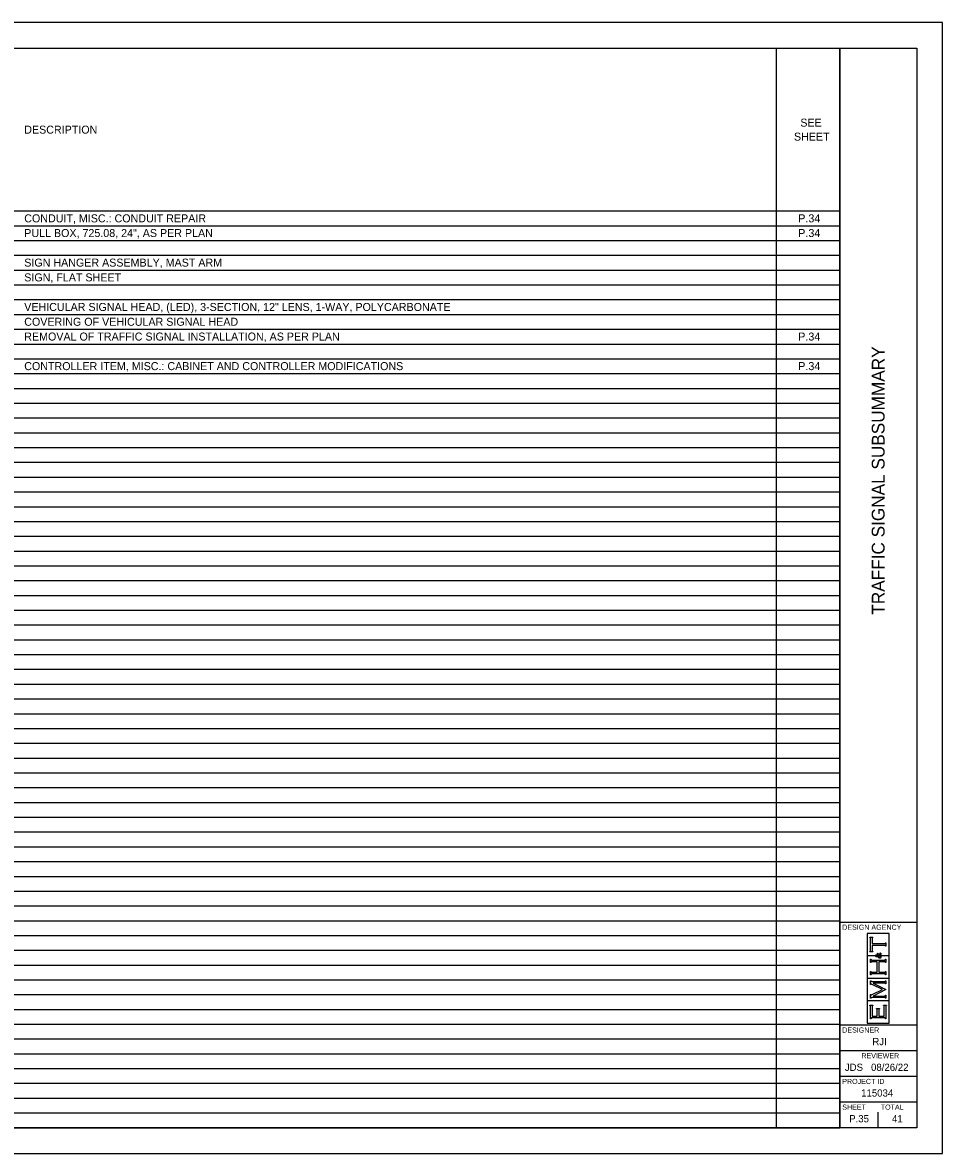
# Model space of a CAD drawing. Extents: x 0 to 34, y 0 to 22.
# Drawn here: x 16.09 to 34, y 0 to 22 of the extents above; entities that cross this region are included whole.
import ezdxf

# ---------------------------------------------------------------- set-up
doc = ezdxf.new("R2010")
doc.units = 0
for name, color, linetype in [('SH_Border', 7, 'Continuous'), ('SH_Cut_Line', 7, 'Continuous'), ('SH_Data', 7, 'Continuous'), ('SH_Text', 7, 'Continuous')]:
    doc.layers.add(name, color=color, linetype=linetype)

msp = doc.modelspace()

# ---------------------------------------------------------------- linework, layer by layer
at = {"layer": 'SH_Border'}
for p, q in [((32, 0.5), (32, 21.5)), ((32, 4.5), (33.5, 4.5)), ((32, 2.5), (33.5, 2.5)), ((32, 2), (33.5, 2)), ((32, 1.5), (33.5, 1.5)), ((32, 1), (33.5, 1))]:
    msp.add_line(p, q, dxfattribs=at)
msp.add_lwpolyline([(1.5, 21.5), (33.5, 21.5), (33.5, 0.5), (1.5, 0.5)], close=True, dxfattribs=at)
at = {"layer": 'SH_Cut_Line'}
msp.add_lwpolyline([(0, 0), (34, 0), (34, 22), (0, 22)], close=True, dxfattribs=at)
at = {"layer": 'SH_Data'}
for p, q in [((32.966, 4.28), (32.534, 4.28)), ((32.534, 4.28), (32.534, 3.848)), ((32.588, 4.199), (32.588, 4.206)), ((32.588, 4.206), (32.644, 4.206)), ((32.594, 4.198), (32.588, 4.199)), ((32.598, 4.196), (32.594, 4.198)), ((32.599, 4.194), (32.598, 4.196)), ((32.601, 4.191), (32.599, 4.194)), ((32.602, 4.187), (32.601, 4.191)), ((32.602, 4.181), (32.602, 4.187)), ((32.602, 3.947), (32.602, 4.181)), ((32.632, 4.191), (32.631, 4.187)), ((32.631, 4.187), (32.631, 4.181)), ((32.631, 4.181), (32.631, 4.081)), ((32.633, 4.194), (32.632, 4.191)), ((32.635, 4.196), (32.633, 4.194)), ((32.639, 4.198), (32.635, 4.196)), ((32.644, 4.199), (32.639, 4.198)), ((32.644, 4.206), (32.644, 4.199)), ((32.966, 3.848), (32.966, 4.28)), ((32.631, 4.081), (32.872, 4.081)), ((32.872, 4.047), (32.631, 4.047)), ((32.631, 4.047), (32.631, 3.947)), ((32.872, 4.081), (32.878, 4.081)), ((32.878, 4.047), (32.872, 4.047)), ((32.878, 4.081), (32.882, 4.082)), ((32.883, 4.046), (32.878, 4.047)), ((32.882, 4.082), (32.885, 4.084)), ((32.885, 4.044), (32.883, 4.046)), ((32.885, 4.084), (32.887, 4.085)), ((32.888, 4.042), (32.885, 4.044)), ((32.887, 4.085), (32.889, 4.089)), ((32.889, 4.039), (32.888, 4.042)), ((32.889, 4.089), (32.891, 4.095)), ((32.891, 4.033), (32.889, 4.039)), ((32.891, 4.095), (32.898, 4.095)), ((32.898, 4.033), (32.891, 4.033)), ((32.898, 4.095), (32.898, 4.033)), ((32.534, 3.848), (32.693, 3.848)), ((32.693, 3.842), (32.534, 3.842)), ((32.534, 3.842), (32.534, 3.41)), ((32.588, 3.928), (32.594, 3.93)), ((32.588, 3.921), (32.588, 3.928)), ((32.644, 3.921), (32.588, 3.921)), ((32.594, 3.93), (32.598, 3.932)), ((32.598, 3.932), (32.599, 3.934)), ((32.599, 3.934), (32.601, 3.937)), ((32.601, 3.937), (32.602, 3.941)), ((32.602, 3.941), (32.602, 3.947)), ((32.602, 3.714), (32.602, 3.776)), ((32.602, 3.776), (32.609, 3.776)), ((32.609, 3.776), (32.611, 3.77)), ((32.611, 3.77), (32.612, 3.766)), ((32.612, 3.766), (32.615, 3.765)), ((32.615, 3.765), (32.617, 3.763)), ((32.617, 3.763), (32.622, 3.762)), ((32.622, 3.762), (32.628, 3.762)), ((32.628, 3.762), (32.872, 3.762)), ((32.631, 3.947), (32.631, 3.941)), ((32.631, 3.941), (32.632, 3.937)), ((32.632, 3.937), (32.633, 3.934)), ((32.633, 3.934), (32.635, 3.932)), ((32.635, 3.932), (32.639, 3.93)), ((32.639, 3.93), (32.644, 3.928)), ((32.644, 3.928), (32.644, 3.921)), ((32.693, 3.848), (32.693, 3.842)), ((32.701, 3.852), (32.703, 3.857)), ((32.701, 3.846), (32.701, 3.852)), ((32.701, 3.84), (32.701, 3.846)), ((32.703, 3.835), (32.701, 3.84)), ((32.703, 3.857), (32.706, 3.861)), ((32.706, 3.83), (32.703, 3.835)), ((32.706, 3.861), (32.71, 3.864)), ((32.707, 3.852), (32.706, 3.849)), ((32.706, 3.849), (32.706, 3.846)), ((32.706, 3.846), (32.706, 3.842)), ((32.706, 3.842), (32.708, 3.839)), ((32.71, 3.824), (32.706, 3.83)), ((32.71, 3.854), (32.707, 3.852)), ((32.708, 3.839), (32.711, 3.837)), ((32.71, 3.864), (32.714, 3.866)), ((32.712, 3.856), (32.71, 3.854)), ((32.717, 3.821), (32.71, 3.824)), ((32.711, 3.837), (32.714, 3.835)), ((32.715, 3.857), (32.712, 3.856)), ((32.714, 3.866), (32.719, 3.866)), ((32.714, 3.835), (32.716, 3.834)), ((32.718, 3.857), (32.715, 3.857)), ((32.716, 3.834), (32.719, 3.834)), ((32.725, 3.821), (32.717, 3.821)), ((32.723, 3.857), (32.718, 3.857)), ((32.719, 3.866), (32.724, 3.866)), ((32.719, 3.834), (32.722, 3.834)), ((32.722, 3.834), (32.724, 3.834)), ((32.727, 3.856), (32.723, 3.857)), ((32.724, 3.866), (32.728, 3.864)), ((32.724, 3.834), (32.727, 3.835)), ((32.728, 3.821), (32.725, 3.821)), ((32.73, 3.853), (32.727, 3.856)), ((32.727, 3.835), (32.73, 3.836)), ((32.728, 3.864), (32.732, 3.861)), ((32.731, 3.822), (32.728, 3.821)), ((32.734, 3.85), (32.73, 3.853)), ((32.73, 3.836), (32.734, 3.837)), ((32.734, 3.822), (32.731, 3.822)), ((32.732, 3.861), (32.736, 3.857)), ((32.737, 3.845), (32.734, 3.85)), ((32.734, 3.837), (32.74, 3.839)), ((32.737, 3.823), (32.734, 3.822)), ((32.736, 3.857), (32.74, 3.851)), ((32.74, 3.839), (32.737, 3.845)), ((32.741, 3.825), (32.737, 3.823)), ((32.738, 3.867), (32.738, 3.898)), ((32.738, 3.898), (32.741, 3.898)), ((32.741, 3.867), (32.738, 3.867)), ((32.74, 3.851), (32.745, 3.842)), ((32.741, 3.898), (32.741, 3.894)), ((32.741, 3.894), (32.742, 3.891)), ((32.742, 3.871), (32.741, 3.869)), ((32.741, 3.869), (32.741, 3.867)), ((32.746, 3.827), (32.741, 3.825)), ((32.742, 3.891), (32.744, 3.889)), ((32.743, 3.872), (32.742, 3.871)), ((32.745, 3.873), (32.743, 3.872)), ((32.744, 3.889), (32.745, 3.887)), ((32.745, 3.887), (32.75, 3.883)), ((32.747, 3.874), (32.745, 3.873)), ((32.745, 3.842), (32.755, 3.848)), ((32.753, 3.815), (32.746, 3.827)), ((32.749, 3.874), (32.747, 3.874)), ((32.756, 3.874), (32.749, 3.874)), ((32.75, 3.883), (32.757, 3.879)), ((32.757, 3.832), (32.751, 3.829)), ((32.751, 3.829), (32.755, 3.824)), ((32.759, 3.808), (32.753, 3.815)), ((32.755, 3.848), (32.765, 3.855)), ((32.755, 3.824), (32.758, 3.819)), ((32.764, 3.87), (32.756, 3.874)), ((32.757, 3.879), (32.765, 3.875)), ((32.762, 3.835), (32.757, 3.832)), ((32.758, 3.819), (32.762, 3.817)), ((32.765, 3.803), (32.759, 3.808)), ((32.766, 3.838), (32.762, 3.835)), ((32.762, 3.817), (32.766, 3.814)), ((32.775, 3.861), (32.764, 3.87)), ((32.765, 3.875), (32.772, 3.87)), ((32.765, 3.855), (32.775, 3.861)), ((32.77, 3.799), (32.765, 3.803)), ((32.77, 3.84), (32.766, 3.838)), ((32.766, 3.814), (32.771, 3.812)), ((32.776, 3.845), (32.77, 3.84)), ((32.776, 3.797), (32.77, 3.799)), ((32.771, 3.812), (32.775, 3.812)), ((32.772, 3.87), (32.779, 3.865)), ((32.775, 3.812), (32.78, 3.812)), ((32.785, 3.851), (32.776, 3.845)), ((32.782, 3.797), (32.776, 3.797)), ((32.779, 3.865), (32.784, 3.869)), ((32.78, 3.812), (32.785, 3.814)), ((32.781, 3.9), (32.783, 3.902)), ((32.785, 3.899), (32.781, 3.9)), ((32.788, 3.797), (32.782, 3.797)), ((32.783, 3.902), (32.79, 3.901)), ((32.784, 3.869), (32.787, 3.873)), ((32.788, 3.897), (32.785, 3.899)), ((32.789, 3.846), (32.785, 3.851)), ((32.785, 3.814), (32.789, 3.817)), ((32.787, 3.873), (32.789, 3.876)), ((32.789, 3.895), (32.788, 3.897)), ((32.793, 3.8), (32.788, 3.797)), ((32.791, 3.892), (32.789, 3.895)), ((32.789, 3.876), (32.791, 3.88)), ((32.794, 3.859), (32.789, 3.855)), ((32.789, 3.855), (32.795, 3.849)), ((32.792, 3.842), (32.789, 3.846)), ((32.789, 3.817), (32.793, 3.821)), ((32.79, 3.901), (32.795, 3.898)), ((32.792, 3.89), (32.791, 3.892)), ((32.791, 3.88), (32.792, 3.883)), ((32.792, 3.886), (32.792, 3.89)), ((32.792, 3.883), (32.792, 3.886)), ((32.793, 3.839), (32.792, 3.842)), ((32.794, 3.837), (32.793, 3.839)), ((32.793, 3.821), (32.795, 3.825)), ((32.797, 3.804), (32.793, 3.8)), ((32.798, 3.864), (32.794, 3.859)), ((32.795, 3.834), (32.794, 3.837)), ((32.795, 3.898), (32.799, 3.894)), ((32.795, 3.849), (32.798, 3.843)), ((32.795, 3.831), (32.795, 3.834)), ((32.795, 3.825), (32.795, 3.831)), ((32.801, 3.809), (32.797, 3.804)), ((32.8, 3.868), (32.798, 3.864)), ((32.798, 3.843), (32.8, 3.839)), ((32.799, 3.894), (32.802, 3.89)), ((32.802, 3.872), (32.8, 3.868)), ((32.8, 3.839), (32.802, 3.834)), ((32.803, 3.815), (32.801, 3.809)), ((32.802, 3.89), (32.803, 3.885)), ((32.803, 3.876), (32.802, 3.872)), ((32.802, 3.834), (32.803, 3.829)), ((32.803, 3.885), (32.803, 3.88)), ((32.803, 3.88), (32.803, 3.876)), ((32.807, 3.842), (32.803, 3.848)), ((32.803, 3.848), (32.966, 3.848)), ((32.803, 3.829), (32.803, 3.823)), ((32.803, 3.823), (32.803, 3.815)), ((32.966, 3.842), (32.807, 3.842)), ((32.872, 3.762), (32.878, 3.762)), ((32.878, 3.762), (32.882, 3.763)), ((32.882, 3.763), (32.885, 3.765)), ((32.885, 3.765), (32.887, 3.766)), ((32.887, 3.766), (32.889, 3.77)), ((32.889, 3.77), (32.891, 3.776)), ((32.891, 3.776), (32.898, 3.776)), ((32.898, 3.776), (32.898, 3.714)), ((32.966, 3.41), (32.966, 3.842)), ((32.609, 3.714), (32.602, 3.714)), ((32.602, 3.477), (32.602, 3.538)), ((32.602, 3.538), (32.609, 3.538)), ((32.61, 3.72), (32.609, 3.714)), ((32.609, 3.538), (32.611, 3.533)), ((32.612, 3.723), (32.61, 3.72)), ((32.611, 3.533), (32.612, 3.529)), ((32.615, 3.725), (32.612, 3.723)), ((32.612, 3.529), (32.615, 3.527)), ((32.617, 3.727), (32.615, 3.725)), ((32.615, 3.527), (32.617, 3.526)), ((32.622, 3.728), (32.617, 3.727)), ((32.617, 3.526), (32.622, 3.525)), ((32.628, 3.728), (32.622, 3.728)), ((32.622, 3.525), (32.628, 3.525)), ((32.732, 3.728), (32.628, 3.728)), ((32.628, 3.525), (32.732, 3.525)), ((32.732, 3.525), (32.732, 3.728)), ((32.872, 3.728), (32.76, 3.728)), ((32.76, 3.728), (32.76, 3.525)), ((32.76, 3.525), (32.872, 3.525)), ((32.878, 3.728), (32.872, 3.728)), ((32.872, 3.525), (32.878, 3.525)), ((32.883, 3.727), (32.878, 3.728)), ((32.878, 3.525), (32.883, 3.525)), ((32.885, 3.725), (32.883, 3.727)), ((32.883, 3.525), (32.885, 3.527)), ((32.888, 3.723), (32.885, 3.725)), ((32.885, 3.527), (32.888, 3.529)), ((32.889, 3.72), (32.888, 3.723)), ((32.888, 3.529), (32.889, 3.533)), ((32.891, 3.714), (32.889, 3.72)), ((32.889, 3.533), (32.891, 3.538)), ((32.898, 3.714), (32.891, 3.714)), ((32.891, 3.538), (32.898, 3.538)), ((32.898, 3.538), (32.898, 3.477)), ((32.534, 3.41), (32.966, 3.41)), ((32.966, 3.405), (32.534, 3.405)), ((32.534, 3.405), (32.534, 2.973)), ((32.609, 3.477), (32.602, 3.477)), ((32.602, 3.283), (32.602, 3.36)), ((32.602, 3.36), (32.609, 3.36)), ((32.61, 3.482), (32.609, 3.477)), ((32.609, 3.36), (32.611, 3.354)), ((32.612, 3.486), (32.61, 3.482)), ((32.611, 3.354), (32.612, 3.351)), ((32.615, 3.488), (32.612, 3.486)), ((32.612, 3.351), (32.615, 3.349)), ((32.617, 3.49), (32.615, 3.488)), ((32.615, 3.349), (32.617, 3.347)), ((32.622, 3.491), (32.617, 3.49)), ((32.617, 3.347), (32.622, 3.346)), ((32.628, 3.491), (32.622, 3.491)), ((32.622, 3.346), (32.628, 3.346)), ((32.872, 3.491), (32.628, 3.491)), ((32.628, 3.346), (32.872, 3.346)), ((32.872, 3.312), (32.649, 3.312)), ((32.649, 3.312), (32.898, 3.186)), ((32.75, 3.5), (32.75, 3.5)), ((32.878, 3.491), (32.872, 3.491)), ((32.872, 3.346), (32.878, 3.346)), ((32.878, 3.312), (32.872, 3.312)), ((32.883, 3.49), (32.878, 3.491)), ((32.878, 3.346), (32.882, 3.347)), ((32.883, 3.311), (32.878, 3.312)), ((32.882, 3.347), (32.885, 3.349)), ((32.885, 3.488), (32.883, 3.49)), ((32.885, 3.31), (32.883, 3.311)), ((32.887, 3.486), (32.885, 3.488)), ((32.885, 3.349), (32.887, 3.351)), ((32.887, 3.308), (32.885, 3.31)), ((32.887, 3.351), (32.889, 3.354)), ((32.889, 3.304), (32.887, 3.308)), ((32.889, 3.482), (32.887, 3.486)), ((32.891, 3.477), (32.889, 3.482)), ((32.889, 3.354), (32.891, 3.36)), ((32.891, 3.298), (32.889, 3.304)), ((32.898, 3.477), (32.891, 3.477)), ((32.891, 3.36), (32.898, 3.36)), ((32.898, 3.36), (32.898, 3.298)), ((32.966, 2.973), (32.966, 3.405)), ((32.609, 3.283), (32.602, 3.283)), ((32.602, 3.017), (32.602, 3.094)), ((32.602, 3.094), (32.609, 3.094)), ((32.612, 3.29), (32.609, 3.283)), ((32.609, 3.094), (32.612, 3.087)), ((32.615, 3.293), (32.612, 3.29)), ((32.612, 3.087), (32.615, 3.083)), ((32.618, 3.293), (32.615, 3.293)), ((32.615, 3.083), (32.618, 3.083)), ((32.621, 3.293), (32.618, 3.293)), ((32.618, 3.083), (32.62, 3.083)), ((32.62, 3.083), (32.625, 3.086)), ((32.626, 3.292), (32.621, 3.293)), ((32.625, 3.086), (32.635, 3.09)), ((32.633, 3.288), (32.626, 3.292)), ((32.831, 3.189), (32.633, 3.288)), ((32.635, 3.09), (32.831, 3.189)), ((32.898, 3.186), (32.649, 3.062)), ((32.898, 3.298), (32.891, 3.298)), ((32.534, 2.973), (32.966, 2.973)), ((32.966, 2.967), (32.534, 2.967)), ((32.534, 2.967), (32.534, 2.535)), ((32.588, 2.874), (32.588, 2.881)), ((32.588, 2.881), (32.644, 2.881)), ((32.594, 2.873), (32.588, 2.874)), ((32.598, 2.871), (32.594, 2.873)), ((32.599, 2.868), (32.598, 2.871)), ((32.601, 2.866), (32.599, 2.868)), ((32.602, 2.862), (32.601, 2.866)), ((32.609, 3.017), (32.602, 3.017)), ((32.602, 2.856), (32.602, 2.862)), ((32.61, 3.023), (32.609, 3.017)), ((32.612, 3.026), (32.61, 3.023)), ((32.615, 3.028), (32.612, 3.026)), ((32.617, 3.03), (32.615, 3.028)), ((32.622, 3.031), (32.617, 3.03)), ((32.628, 3.031), (32.622, 3.031)), ((32.872, 3.031), (32.628, 3.031)), ((32.632, 2.866), (32.631, 2.862)), ((32.631, 2.862), (32.631, 2.856)), ((32.633, 2.868), (32.632, 2.866)), ((32.635, 2.871), (32.633, 2.868)), ((32.639, 2.873), (32.635, 2.871)), ((32.644, 2.874), (32.639, 2.873)), ((32.644, 2.881), (32.644, 2.874)), ((32.649, 3.062), (32.872, 3.062)), ((32.855, 2.877), (32.855, 2.884)), ((32.855, 2.884), (32.912, 2.884)), ((32.861, 2.876), (32.855, 2.877)), ((32.865, 2.874), (32.861, 2.876)), ((32.867, 2.872), (32.865, 2.874)), ((32.868, 2.869), (32.867, 2.872)), ((32.869, 2.865), (32.868, 2.869)), ((32.869, 2.859), (32.869, 2.865)), ((32.872, 3.062), (32.878, 3.062)), ((32.878, 3.031), (32.872, 3.031)), ((32.878, 3.062), (32.882, 3.063)), ((32.883, 3.03), (32.878, 3.031)), ((32.882, 3.063), (32.885, 3.065)), ((32.885, 3.028), (32.883, 3.03)), ((32.885, 3.065), (32.887, 3.067)), ((32.887, 3.026), (32.885, 3.028)), ((32.887, 3.067), (32.889, 3.07)), ((32.889, 3.023), (32.887, 3.026)), ((32.889, 3.07), (32.891, 3.076)), ((32.891, 3.017), (32.889, 3.023)), ((32.891, 3.076), (32.898, 3.076)), ((32.898, 3.017), (32.891, 3.017)), ((32.898, 3.076), (32.898, 3.017)), ((32.899, 2.869), (32.898, 2.865)), ((32.898, 2.865), (32.898, 2.858)), ((32.901, 2.871), (32.899, 2.869)), ((32.903, 2.874), (32.901, 2.871)), ((32.906, 2.876), (32.903, 2.874)), ((32.912, 2.877), (32.906, 2.876)), ((32.912, 2.884), (32.912, 2.877)), ((32.966, 2.535), (32.966, 2.967)), ((32.602, 2.621), (32.602, 2.856)), ((32.631, 2.856), (32.631, 2.669)), ((32.631, 2.669), (32.732, 2.669)), ((32.718, 2.81), (32.718, 2.816)), ((32.718, 2.816), (32.774, 2.816)), ((32.723, 2.808), (32.718, 2.81)), ((32.727, 2.806), (32.723, 2.808)), ((32.729, 2.804), (32.727, 2.806)), ((32.731, 2.801), (32.729, 2.804)), ((32.732, 2.797), (32.731, 2.801)), ((32.732, 2.791), (32.732, 2.797)), ((32.732, 2.669), (32.732, 2.791)), ((32.761, 2.801), (32.76, 2.797)), ((32.76, 2.797), (32.76, 2.791)), ((32.76, 2.791), (32.76, 2.669)), ((32.76, 2.669), (32.869, 2.669)), ((32.763, 2.804), (32.761, 2.801)), ((32.765, 2.806), (32.763, 2.804)), ((32.768, 2.808), (32.765, 2.806)), ((32.774, 2.81), (32.768, 2.808)), ((32.774, 2.816), (32.774, 2.81)), ((32.869, 2.669), (32.869, 2.859)), ((32.898, 2.858), (32.898, 2.621)), ((32.534, 2.535), (32.966, 2.535)), ((32.609, 2.621), (32.602, 2.621)), ((32.611, 2.626), (32.609, 2.621)), ((32.612, 2.63), (32.611, 2.626)), ((32.615, 2.632), (32.612, 2.63)), ((32.617, 2.634), (32.615, 2.632)), ((32.622, 2.635), (32.617, 2.634)), ((32.628, 2.635), (32.622, 2.635)), ((32.872, 2.635), (32.628, 2.635)), ((32.878, 2.635), (32.872, 2.635)), ((32.883, 2.634), (32.878, 2.635)), ((32.885, 2.632), (32.883, 2.634)), ((32.887, 2.63), (32.885, 2.632)), ((32.889, 2.627), (32.887, 2.63)), ((32.891, 2.621), (32.889, 2.627)), ((32.898, 2.621), (32.891, 2.621)), ((32.375, 0.675), (32.375, 0.675)), ((32.75, 0.5), (32.75, 0.8))]:
    msp.add_line(p, q, dxfattribs=at)
at = {"layer": 'SH_Text'}
for p, q in [((1.5, 21.5), (32, 21.5)), ((30.765, 21.5), (30.765, 0.5)), ((32, 21.5), (32, 0.5)), ((1.5, 18.336), (32, 18.336)), ((1.5, 18.048), (32, 18.048)), ((1.5, 17.76), (32, 17.76)), ((1.5, 17.473), (32, 17.473)), ((1.5, 17.185), (32, 17.185)), ((1.5, 16.897), (32, 16.897)), ((1.5, 16.61), (32, 16.61)), ((1.5, 16.322), (32, 16.322)), ((1.5, 16.034), (32, 16.034)), ((1.5, 15.747), (32, 15.747)), ((1.5, 15.459), (32, 15.459)), ((1.5, 15.171), (32, 15.171)), ((1.5, 14.884), (32, 14.884)), ((1.5, 14.596), (32, 14.596)), ((1.5, 14.308), (32, 14.308)), ((1.5, 14.021), (32, 14.021)), ((1.5, 13.733), (32, 13.733)), ((1.5, 13.445), (32, 13.445)), ((1.5, 13.158), (32, 13.158)), ((1.5, 12.87), (32, 12.87)), ((1.5, 12.582), (32, 12.582)), ((1.5, 12.295), (32, 12.295)), ((1.5, 12.007), (32, 12.007)), ((1.5, 11.719), (32, 11.719)), ((1.5, 11.432), (32, 11.432)), ((1.5, 11.144), (32, 11.144)), ((1.5, 10.856), (32, 10.856)), ((1.5, 10.568), (32, 10.568)), ((1.5, 10.281), (32, 10.281)), ((1.5, 9.993), (32, 9.993)), ((1.5, 9.705), (32, 9.705)), ((1.5, 9.418), (32, 9.418)), ((1.5, 9.13), (32, 9.13)), ((1.5, 8.842), (32, 8.842)), ((1.5, 8.555), (32, 8.555)), ((1.5, 8.267), (32, 8.267)), ((1.5, 7.979), (32, 7.979)), ((1.5, 7.692), (32, 7.692)), ((1.5, 7.404), (32, 7.404)), ((1.5, 7.116), (32, 7.116)), ((1.5, 6.829), (32, 6.829)), ((1.5, 6.541), (32, 6.541)), ((1.5, 6.253), (32, 6.253)), ((1.5, 5.966), (32, 5.966)), ((1.5, 5.678), (32, 5.678)), ((1.5, 5.39), (32, 5.39)), ((1.5, 5.103), (32, 5.103)), ((1.5, 4.815), (32, 4.815)), ((1.5, 4.527), (32, 4.527)), ((1.5, 4.24), (32, 4.24)), ((1.5, 3.952), (32, 3.952)), ((1.5, 3.664), (32, 3.664)), ((1.5, 3.377), (32, 3.377)), ((1.5, 3.089), (32, 3.089)), ((1.5, 2.801), (32, 2.801)), ((1.5, 2.514), (32, 2.514)), ((1.5, 2.226), (32, 2.226)), ((1.5, 1.938), (32, 1.938)), ((1.5, 1.651), (32, 1.651)), ((1.5, 1.363), (32, 1.363)), ((1.5, 1.075), (32, 1.075)), ((1.5, 0.788), (32, 0.788)), ((1.5, 0.5), (32, 0.5))]:
    msp.add_line(p, q, dxfattribs=at)

# ---------------------------------------------------------------- texts
at = {"layer": 'SH_Data'}
msp.add_text('TRAFFIC SIGNAL SUBSUMMARY', height=0.25, rotation=90, dxfattribs=at).set_placement((32.875, 10.481))
for s, height, p in [('DESIGN AGENCY', 0.1, (32.05, 4.35)), ('DESIGNER', 0.1, (32.05, 2.35)), ('RJI', 0.14, (32.636, 2.105)), ('REVIEWER', 0.1, (32.422, 1.85)), ('JDS', 0.14, (32.1, 1.605)), ('08/26/22', 0.14, (32.611, 1.605)), ('PROJECT ID', 0.1, (32.05, 1.35)), ('115034', 0.14, (32.418, 1.105)), ('SHEET', 0.1, (32.05, 0.85)), ('TOTAL', 0.1, (32.8, 0.85)), ('P.35', 0.14, (32.185, 0.605)), ('41', 0.14, (33.019, 0.605))]:
    msp.add_text(s, height=height, dxfattribs=at).set_placement(p)
at = {"layer": 'SH_Text'}
for s, height, p in [('SEE                    ', 0.15568, (31.234, 19.976)), ('DESCRIPTION', 0.15568, (16.124, 19.84)), ('SHEET', 0.1557, (31.11, 19.704)), ('CONDUIT, MISC.: CONDUIT REPAIR', 0.15568, (16.124, 18.114)), ('P.34', 0.1557, (31.194, 18.114)), ('PULL BOX, 725.08, 24", AS PER PLAN', 0.15568, (16.124, 17.828)), ('P.34', 0.1557, (31.194, 17.828)), ('SIGN HANGER ASSEMBLY, MAST ARM', 0.15568, (16.124, 17.253)), ('SIGN, FLAT SHEET', 0.15568, (16.124, 16.965)), ('VEHICULAR SIGNAL HEAD, (LED), 3-SECTION, 12" LENS, 1-WAY, POLYCARBONATE', 0.15568, (16.124, 16.39)), ('COVERING OF VEHICULAR SIGNAL HEAD', 0.15568, (16.124, 16.102)), ('REMOVAL OF TRAFFIC SIGNAL INSTALLATION, AS PER PLAN', 0.15568, (16.124, 15.814)), ('P.34', 0.1557, (31.194, 15.814)), ('CONTROLLER ITEM, MISC.: CABINET AND CONTROLLER MODIFICATIONS', 0.15568, (16.124, 15.239)), ('P.34', 0.1557, (31.194, 15.239))]:
    msp.add_text(s, height=height, dxfattribs=at).set_placement(p)

doc.saveas('drawing.dxf')
